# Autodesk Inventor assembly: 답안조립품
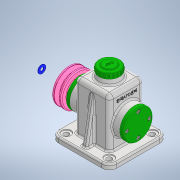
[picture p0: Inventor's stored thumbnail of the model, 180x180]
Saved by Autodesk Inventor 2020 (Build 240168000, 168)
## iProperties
Created: 2021-07
Part Number: 답안조립품
Document SubType Name: Assembly
Designer: Owner
Author: Owner
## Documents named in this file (13)
- C:\Users\Owner\Desktop\710715V1012\답안조립품.iam
- C:\Users\Owner\Desktop\710715V1012\본체.ipt
- C:\Users\Owner\Desktop\710715V1012\베어링 15 x 35 x 11.ipt
- C:\Users\Owner\Desktop\710715V1012\축.ipt
- C:\Users\Owner\Desktop\710715V1012\멈춤링 15 x 1.ipt
- C:\Users\Owner\Desktop\710715V1012\앞커버.ipt
- C:\Users\Owner\Desktop\710715V1012\뒤커버.ipt
- C:\Users\Owner\Desktop\710715V1012\오일실 15 25 7.ipt
- C:\Users\Owner\Desktop\710715V1012\볼트 M4 x 10.ipt
- C:\Users\Owner\Desktop\710715V1012\상부캡.ipt
- C:\Users\Owner\Desktop\710715V1012\키 5 x 5 x 14.ipt
- C:\Users\Owner\Desktop\710715V1012\V-벨트풀리.ipt
- C:\Users\Owner\Desktop\710715V1012\와셔.ipt
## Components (1 placed, 1 different names)
1. V-벨트풀리:1 — 플러쉬:1
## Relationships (1: Flush 1)
- 플러쉬:1 [Flush]: V-벨트풀리:1
